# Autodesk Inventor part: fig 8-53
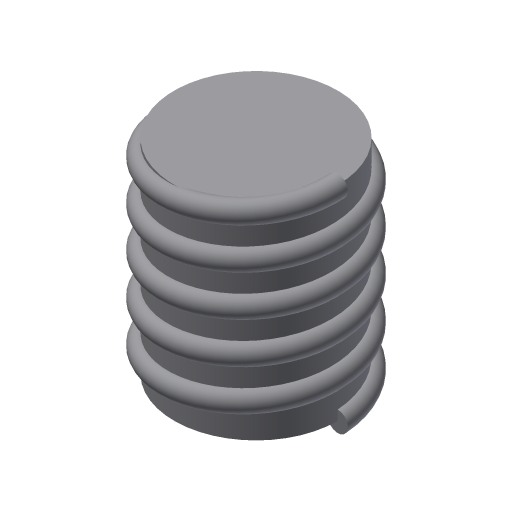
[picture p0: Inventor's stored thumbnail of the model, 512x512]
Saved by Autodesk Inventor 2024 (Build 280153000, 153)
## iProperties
Shininess: 77.0
Length Units: 11269
Angle Units: 11279
Time Units: 11290
Mass Units: 11283
Length Display Precision: 3
Angle Display Precision: 2
Created: 2002-01
Part Number: fig 8-53
Document SubType Name: Modeling
Designer: CADSoft
Density: 1 g/cm^3
Material: Generic
Appearance: Default
Density: 0.0
Volumn: 0.0
Area: 0.0
PropertySet Name: Model Information
Control State: 0
Master: False
Checked Out: False
Author: CADSoft
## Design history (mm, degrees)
sketch "Sketch4"
  geometry: C1 r 20 at (0, 0)
  constraints: 1 centre point
  dimensions: "d44" = 40 diameter of C1
sketch "Sketch2"
  geometry: C1 r 2.5 at (-20, -0.092); 1 further point
  constraints: 1 centre point, 1 other
  dimensions: "d0" = 5 diameter of C1; "d43" = 20 horizontal distance of C1.centre point (0, 0)
extrude "Extrusion2" join sketch "Sketch4" distance "d45" = 50; taper "d46" = 0 deg
coil "Coil6" pitch "d47" = 10; turns "d49" = 5; dims "d48" = 10, "d50" = 0, angle "d51" = 90 deg, angle "d52" = 90 deg, "d53" = 0, "d54" = 0
body "Solid1"
